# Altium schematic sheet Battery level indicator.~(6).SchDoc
size A3; SheetNumber: 3; SheetTotal: 3
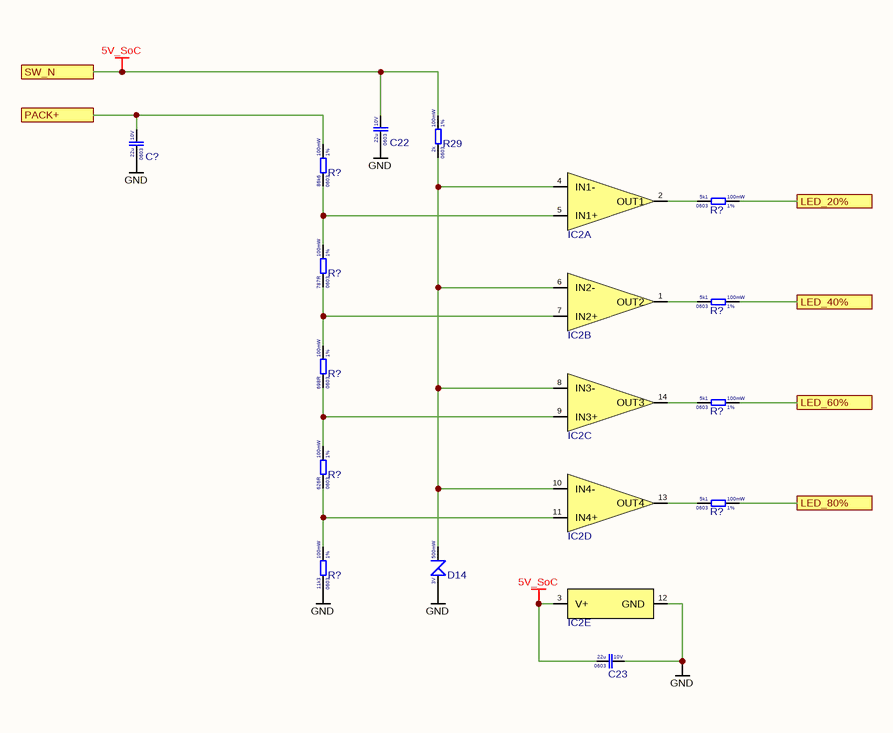
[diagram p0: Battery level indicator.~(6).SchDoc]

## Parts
(Parts that share a designator on the sheet are numbered #1, #2 ... from top to bottom, then left to right.)
C22  Voltage Rating: 10V  Case Code (Imperial): 0603  Capacitance: 22u  [CAP 0603]  (hidden comment: CGA0603X5R226M100JT)
C23  Voltage Rating: 10V  Case Code (Imperial): 0603  Capacitance: 22u  [CAP 0603]  (hidden comment: CGA0603X5R226M100JT)
C?  Voltage Rating: 10V  Case Code (Imperial): 0603  Capacitance: 22u  [CAP 0603]  (hidden comment: CGA0603X5R226M100JT)
D14  Power Rating: 500mW  Reverse Voltage: 3V  [SOD-123]  (hidden comment: BZT52C3V0)
IC2  LM339LVPWR  [TSSOP-14]  (value not drawn)  (parts A,B,C,D,E of 5)
R29  Resistance Tolerance: 1%  Resistance: 2k  Power Rating: 100mW  Case Code (Imperial): 0603  [RES_0603]  (hidden comment: 0603WAF2001T5E)
R?#1  Resistance Tolerance: 1%  Resistance: 86k6  Power Rating: 100mW  Case Code (Imperial): 0603  [RES_0603]  (hidden comment: 0603WAF8662T5E)
R?#2  Resistance Tolerance: 1%  Resistance: 5k1  Power Rating: 100mW  Case Code (Imperial): 0603  [RES_0603]  (hidden comment: 0603WAF5101T5E)
R?#3  Resistance Tolerance: 1%  Resistance: 787R  Power Rating: 100mW  Case Code (Imperial): 0603  [RES_0603]  (hidden comment: FRC0603F7870TS)
R?#4  Resistance Tolerance: 1%  Resistance: 5k1  Power Rating: 100mW  Case Code (Imperial): 0603  [RES_0603]  (hidden comment: 0603WAF5101T5E)
R?#5  Resistance Tolerance: 1%  Resistance: 698R  Power Rating: 100mW  Case Code (Imperial): 0603  [RES_0603]  (hidden comment: RC0603FR-07698RL)
R?#6  Resistance Tolerance: 1%  Resistance: 5k1  Power Rating: 100mW  Case Code (Imperial): 0603  [RES_0603]  (hidden comment: 0603WAF5101T5E)
R?#7  Resistance Tolerance: 1%  Resistance: 626R  Power Rating: 100mW  Case Code (Imperial): 0603  [RES_0603]  (hidden comment: RT0603BRD07626RL)
R?#8  Resistance Tolerance: 1%  Resistance: 5k1  Power Rating: 100mW  Case Code (Imperial): 0603  [RES_0603]  (hidden comment: 0603WAF5101T5E)
R?#9  Resistance Tolerance: 1%  Resistance: 11k3  Power Rating: 100mW  Case Code (Imperial): 0603  [RES_0603]  (hidden comment: FRC0603F1132TS)

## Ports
LED_20% (see Arhitecture[8C]), LED_40% (see Arhitecture[8C]), LED_60% (see Arhitecture[8C]), LED_80% (see Arhitecture[8D]), PACK+ (see Arhitecture[7C], Charger[8A]), SW_N (see Arhitecture[7D])

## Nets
5V_SoC: C22.2 C23.1 IC2.3(V+) R29.2 ; port SW_N
GND: C22.1 C23.2 C?.1 D14.A IC2.12(GND) R?#9.1
LED_20%: R?#2.2 ; port LED_20%
LED_40%: R?#4.2 ; port LED_40%
LED_60%: R?#6.2 ; port LED_60%
LED_80%: R?#8.2 ; port LED_80%
PACK+: C?.2 R?#1.2 ; port PACK+
NetD14_K: D14.K IC2.4(IN1-) IC2.6(IN2-) IC2.8(IN3-) IC2.10(IN4-) R29.1
NetIC2_1: IC2.1(OUT2) R?#4.1
NetIC2_2: IC2.2(OUT1) R?#2.1
NetIC2_5: IC2.5(IN1+) R?#1.1 R?#3.2
NetIC2_7: IC2.7(IN2+) R?#3.1 R?#5.2
NetIC2_9: IC2.9(IN3+) R?#5.1 R?#7.2
NetIC2_11: IC2.11(IN4+) R?#7.1 R?#9.2
NetIC2_13: IC2.13(OUT4) R?#8.1
NetIC2_14: IC2.14(OUT3) R?#6.1

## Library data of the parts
C22 C23 C? = CGA0603X5R226M100JT: Cap 22uF 10V 0603 X5R; Manufacturer: HRE
D14 = BZT52C3V0: Zener 3.0V 500mW SOD-123; Manufacturer: Shandong Jingdao Microelectronics
IC2 = LM339LVPWR: Comparator Quad 1.65~5.5V TSSOP-14; Manufacturer: Texas Instruments
R29 = 0603WAF2001T5E: Res 2k 0603 1% 100mW 75V; Manufacturer: Uni-Royal
R?#1 = 0603WAF8662T5E: Res 86k6 0603 1% 100mW 75V; Manufacturer: Uni-Royal
R?#2 R?#4 R?#6 R?#8 = 0603WAF5101T5E: Res 5k1 0603 1% 100mW 75V; Manufacturer: Uni-Royal
R?#3 = FRC0603F7870TS: Res 787R 0603 1% 100mW 75V; Manufacturer: FOJAN
R?#5 = RC0603FR-07698RL: Res 698R 0603 1% 100mW 75V; Manufacturer: YAGEO
R?#7 = RT0603BRD07626RL: Res 626R 0603 1% 100mW 75V; Manufacturer: YAGEO
R?#9 = FRC0603F1132TS: Res 11k3 0603 1% 100mW 75V; Manufacturer: Fojan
